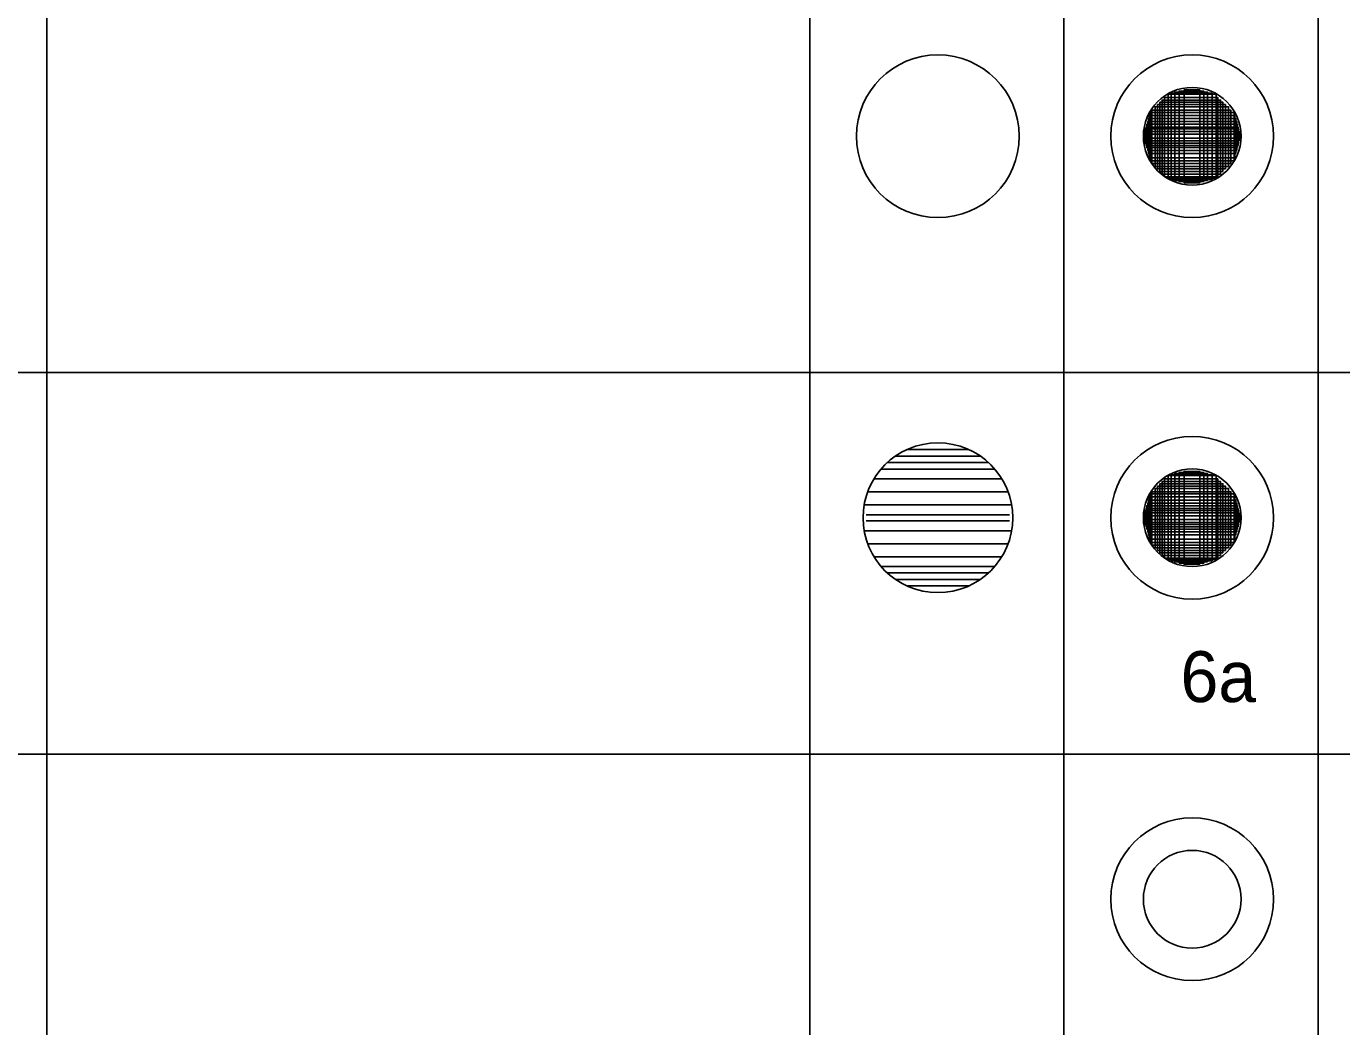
# Model space of a CAD drawing. Extents: x -28 to 822, y 61 to 665.
# Drawn here: x 82.3 to 134, y 221 to 260.4 of the extents above; entities that cross this region are included whole.
import ezdxf

# ---------------------------------------------------------------- set-up
doc = ezdxf.new("R2010")
doc.units = 0
doc.layers.add('KOLEJIŠTĚ', color=7, linetype='Continuous')

# ---------------------------------------------------------------- blocks, each defined once
blk = doc.blocks.new('HR3')
for radius in [2.5, 1.5]:
    blk.add_circle((0, 0), radius)
blk = doc.blocks.new('ZT72')
at = {"xscale": 0.8, "yscale": 0.8000000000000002}
blk.add_blockref('HR3', (0, 0), dxfattribs=at)
blk = doc.blocks.new('HR6')
for p, q in [((-0.95, 2.095), (0.95, 2.095)), ((-1.555, 1.695), (1.555, 1.695)), ((-1.304, 1.895), (1.304, 1.895)), ((-1.748, 1.495), (1.748, 1.495)), ((-1.962, 1.2), (1.962, 1.2)), ((-2.156, 0.8), (2.156, 0.8)), ((-2.265, 0.4), (2.265, 0.4)), ((-2.2, 0.09), (2.2, 0.09)), ((-2.265, -0.4), (2.265, -0.4)), ((-2.2, -0.09), (2.2, -0.09)), ((-2.156, -0.8), (2.156, -0.8)), ((-1.962, -1.2), (1.962, -1.2)), ((-1.748, -1.495), (1.748, -1.495)), ((-1.555, -1.695), (1.555, -1.695)), ((-1.304, -1.895), (1.304, -1.895)), ((-0.95, -2.095), (0.95, -2.095))]:
    blk.add_line(p, q)
for start, end in [(0, 180), (180, 0)]:
    blk.add_arc((0, 0), 2.3, start, end)
blk = doc.blocks.new('ZT75')
at = {"xscale": 0.8, "yscale": 0.8000000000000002}
blk.add_blockref('HR6', (0, 0), dxfattribs=at)

msp = doc.modelspace()

# ---------------------------------------------------------------- linework, layer by layer
for p, q in [((113.116, 381.738), (113.116, 111.738)), ((123.116, 381.738), (123.116, 111.738)), ((133.116, 381.738), (133.116, 141.738)), ((83.116, 336.738), (83.116, 111.738)), ((133.116, 336.738), (133.116, 111.738)), ((5.068, 246.738), (540.616, 246.738)), ((5.068, 246.738), (540.616, 246.738)), ((5.068, 231.738), (292.72, 231.738))]:
    msp.add_line(p, q)
for points in [[(129.101, 254.383), (127.208, 254.383), (127.208, 257.692), (129.101, 257.692)], [(128.937, 254.337), (127.326, 254.337), (127.326, 257.719), (128.937, 257.719)], [(128.764, 254.292), (127.472, 254.292), (127.472, 257.765), (128.764, 257.765)], [(128.609, 254.246), (127.645, 254.246), (127.645, 257.81), (128.609, 257.81)], [(128.455, 254.201), (127.836, 254.201), (127.836, 257.856), (128.455, 257.856)], [(129.592, 254.846), (126.698, 254.846), (126.698, 257.183), (129.592, 257.183)], [(129.465, 254.746), (126.799, 254.746), (126.799, 257.274), (129.465, 257.274)], [(129.365, 254.646), (126.89, 254.646), (126.89, 257.365), (129.365, 257.365)], [(129.274, 254.546), (126.971, 254.546), (126.971, 257.456), (129.274, 257.456)], [(129.165, 254.437), (127.072, 254.437), (127.072, 257.556), (129.165, 257.556)], [(129.911, 255.474), (126.407, 255.474), (126.407, 256.61), (129.911, 256.61)], [(129.874, 255.355), (126.435, 255.355), (126.435, 256.728), (129.874, 256.728)], [(129.829, 255.183), (126.471, 255.183), (126.471, 256.847), (129.829, 256.847)], [(129.802, 255.064), (126.507, 255.064), (126.507, 256.965), (129.802, 256.965)], [(129.683, 254.955), (126.571, 254.955), (126.571, 257.056), (129.683, 257.056)], [(130.047, 255.956), (126.28, 255.956), (126.28, 256.11), (130.047, 256.11)], [(129.984, 255.765), (126.307, 255.765), (126.307, 256.319), (129.984, 256.319)], [(130.011, 255.846), (126.307, 255.846), (126.307, 256.219), (130.011, 256.219)], [(129.965, 255.674), (126.353, 255.674), (126.353, 256.392), (129.965, 256.392)], [(129.938, 255.583), (126.371, 255.583), (126.371, 256.501), (129.938, 256.501)], [(129.101, 239.383), (127.208, 239.383), (127.208, 242.692), (129.101, 242.692)], [(128.937, 239.337), (127.326, 239.337), (127.326, 242.719), (128.937, 242.719)], [(128.764, 239.292), (127.472, 239.292), (127.472, 242.765), (128.764, 242.765)], [(128.609, 239.246), (127.645, 239.246), (127.645, 242.81), (128.609, 242.81)], [(128.455, 239.201), (127.836, 239.201), (127.836, 242.856), (128.455, 242.856)], [(129.592, 239.846), (126.698, 239.846), (126.698, 242.183), (129.592, 242.183)], [(129.465, 239.746), (126.799, 239.746), (126.799, 242.274), (129.465, 242.274)], [(129.365, 239.646), (126.89, 239.646), (126.89, 242.365), (129.365, 242.365)], [(129.274, 239.546), (126.971, 239.546), (126.971, 242.456), (129.274, 242.456)], [(129.165, 239.437), (127.072, 239.437), (127.072, 242.556), (129.165, 242.556)], [(129.911, 240.474), (126.407, 240.474), (126.407, 241.61), (129.911, 241.61)], [(129.874, 240.355), (126.435, 240.355), (126.435, 241.728), (129.874, 241.728)], [(129.829, 240.183), (126.471, 240.183), (126.471, 241.847), (129.829, 241.847)], [(129.802, 240.064), (126.507, 240.064), (126.507, 241.965), (129.802, 241.965)], [(129.683, 239.955), (126.571, 239.955), (126.571, 242.056), (129.683, 242.056)], [(130.047, 240.956), (126.28, 240.956), (126.28, 241.11), (130.047, 241.11)], [(129.984, 240.765), (126.307, 240.765), (126.307, 241.319), (129.984, 241.319)], [(130.011, 240.846), (126.307, 240.846), (126.307, 241.219), (130.011, 241.219)], [(129.965, 240.674), (126.353, 240.674), (126.353, 241.392), (129.965, 241.392)], [(129.938, 240.583), (126.371, 240.583), (126.371, 241.501), (129.938, 241.501)]]:
    msp.add_lwpolyline(points, close=True)
msp.add_circle((118.157, 256.031), 3.2)

# ---------------------------------------------------------------- block references
at = {"layer": 'KOLEJIŠTĚ', "xscale": 1.600000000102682, "yscale": 1.600000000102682}
for name, p in [('ZT72', (128.157, 256.031)), ('ZT72', (128.157, 241.031)), ('ZT75', (118.157, 241.031)), ('ZT72', (128.157, 226.031))]:
    msp.add_blockref(name, p, dxfattribs=at)

# ---------------------------------------------------------------- texts
msp.add_text('6a', height=2).set_placement((127.698, 233.784))

doc.saveas('drawing.dxf')
